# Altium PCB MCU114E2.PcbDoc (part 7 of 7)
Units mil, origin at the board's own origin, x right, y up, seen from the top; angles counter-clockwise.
Board outline 4153.94 x 2313.28 mil, 8 copper layers (Top Layer, GND 2, Signal Layer 3, Power 4, Power 5, Signal Layer 6, GND 7, Bottom), stack 61.2 mil thick; 444 components, 418 nets, 1811 pads, 981 vias.
Unrouted connection lines stored in the file: 3.
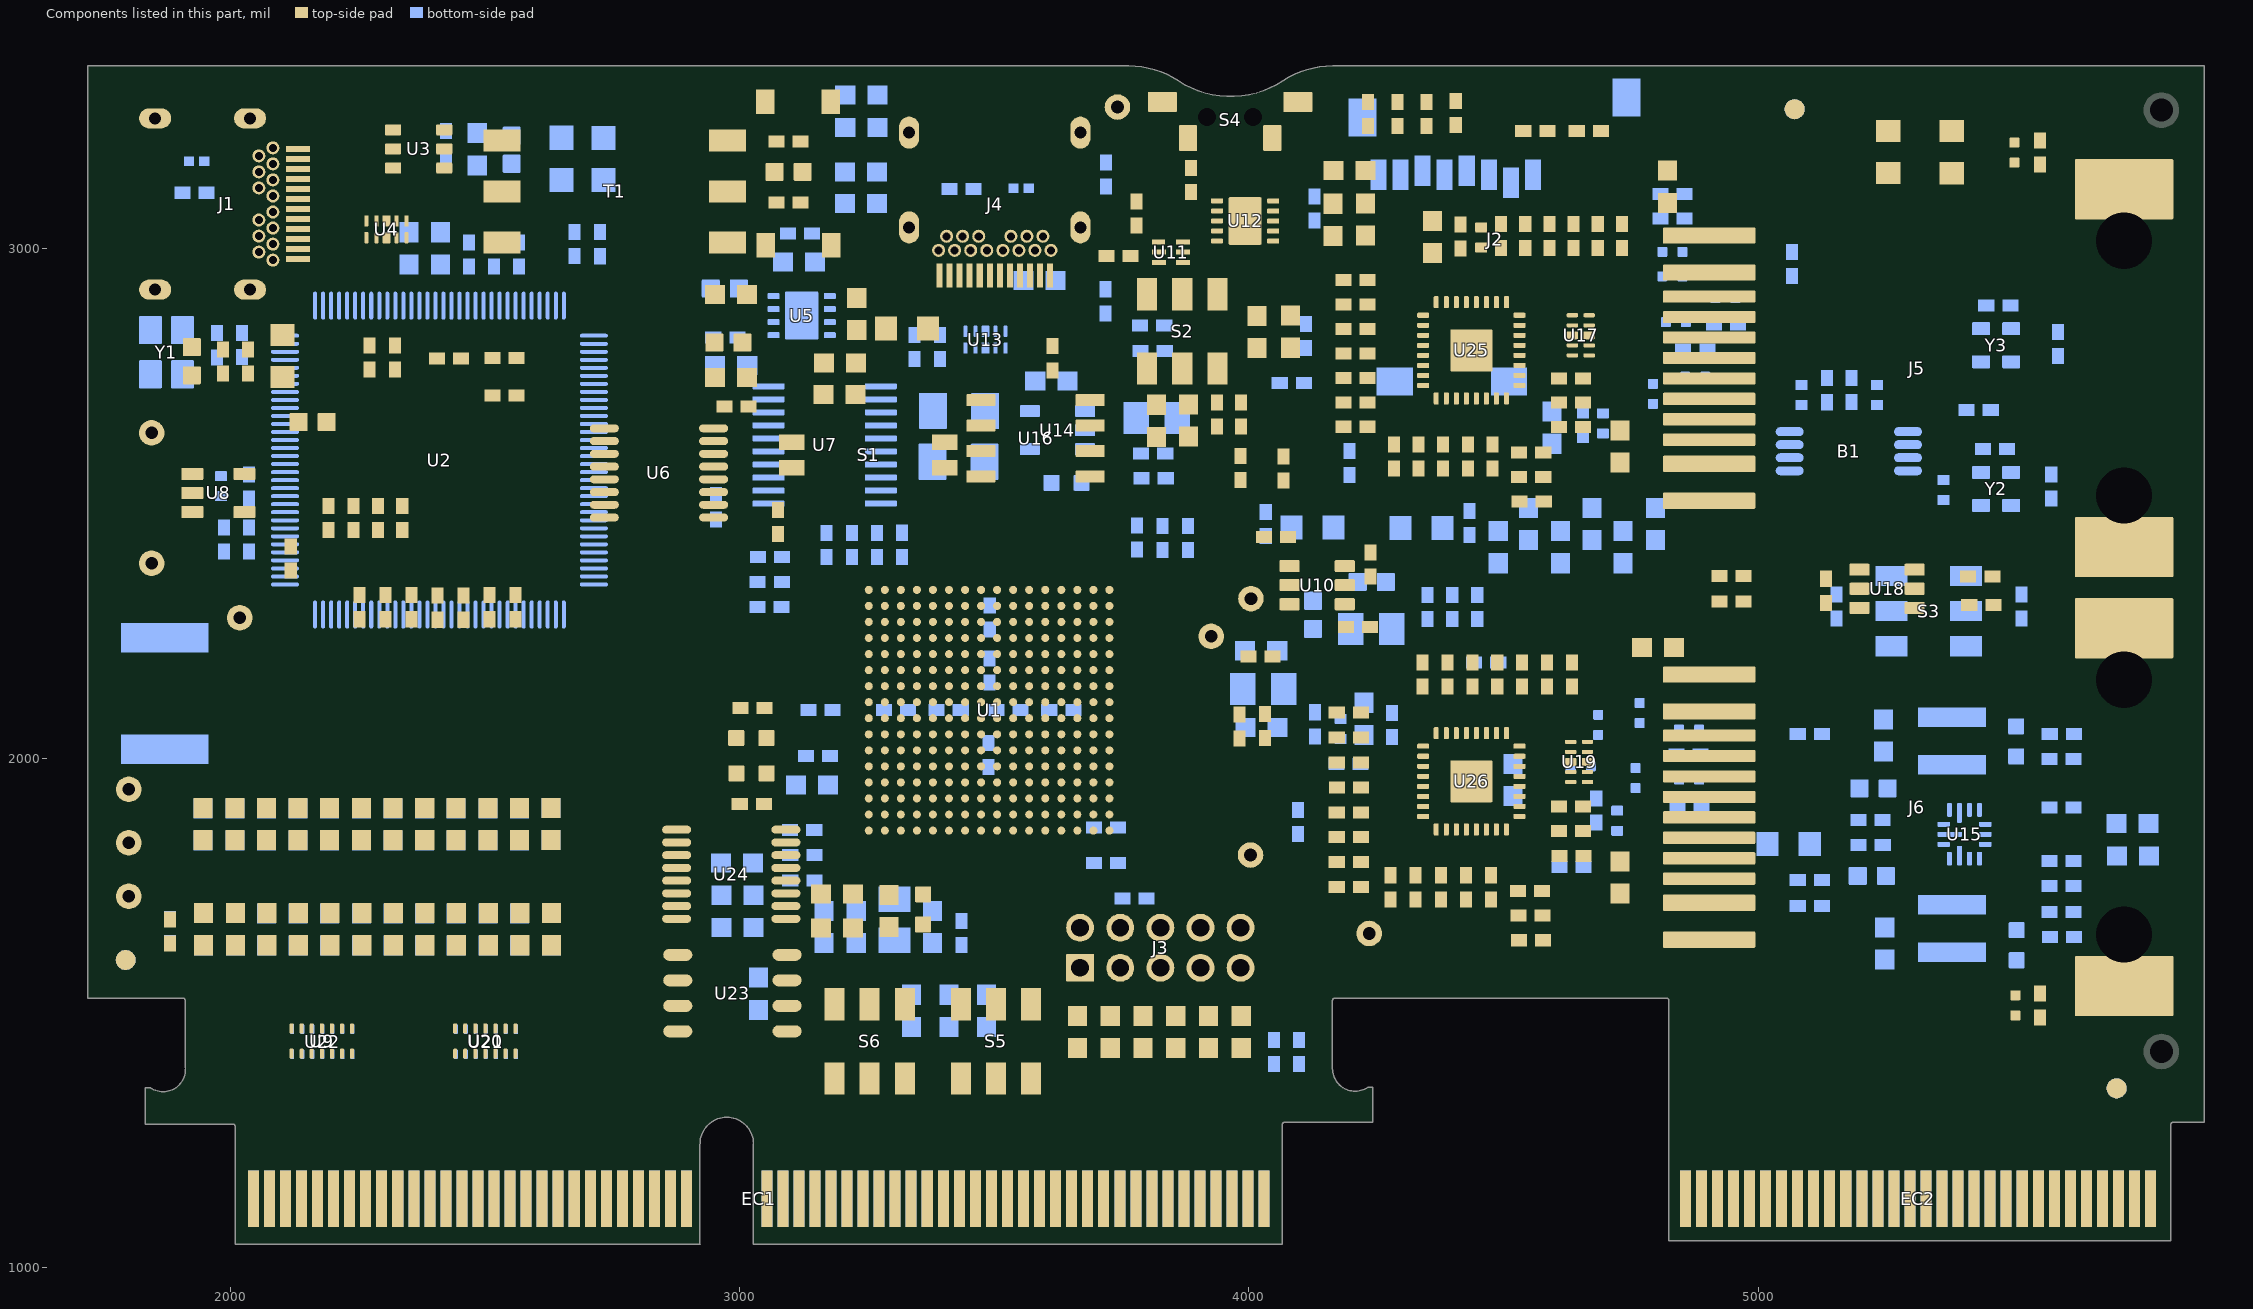
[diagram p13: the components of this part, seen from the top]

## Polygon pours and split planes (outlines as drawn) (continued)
5V0 on Bottom "BOTTOM_5V0_P229" (solid, remove dead copper, pour order 229): 5218.85,1959.23 5218.85,1896 5301,1896 5347,1896 5364.53,1878.47 5385.37,1878.47 5385.37,1940.04 5366.18,1959.23
5V0 on Bottom "BOTTOM_5V0_P230" (solid, remove dead copper, pour order 230): 5851.44,1971.69 5740.44,1971.69 5740.44,1851.69 5851.44,1851.69
EMU_5V0 on Bottom "BOTTOM_EMU_5V0_P231" (solid, remove dead copper, pour order 231): 2345.08,3216.85 2355.04,3216.85 2402.43,3216.85 2402.43,3207.9 2456.01,3207.9 2456.01,3189.27 2617.83,3189.27 2617.83,3074.27 2410.83,3074.27 2345.08,3140.02
5V0 on Bottom "BOTTOM_5V0_P232" (solid, remove dead copper, pour order 232): 3232.19,3339.27 3232.19,3232 3382,3232 3462.73,3151.27 3821.06,3151.27 3821.06,3339.27
EMU_GND on GND 2 "GND_2_EMU_GND_P206" (solid, remove dead copper, pour order 206): 1745.23,3346.77 2776.83,3346.77 2776.83,2365.27 2614.83,2203.27 1743.04,2203.27
ETH1_EARTH on GND 2 "GND_2_ETH1_EARTH_P172" (solid, remove dead copper, pour order 172): 5466,3228 5468,3230 5623,3230 5623,3332.84 5622.83,3333.01 5625.05,3335.23 5851.76,3335.23 5851.76,1337.49 5849.54,1335.27 5551.33,1335.27 5551.33,1598.1 5631.83,1598.1 5631.83,1728.84 5631.45,1729.22 5631.38,1729.16 4983.08,1729.16 4983.08,1806.03 5628.83,1806.03 5628.83,2186.78 5547.83,2267.78 5542.42,2267.78 5542.42,2430.79 5617.42,2505.79 5617.42,2593.86 5612.01,2599.27 4983.08,2599.27 4983.08,2696.27 5622.83,2696.27 5622.83,3075.27 5621.71,3074.15 5466.26,3074.15 5466.26,3229.26 5467,3230
GND on GND 2 "GND_2_GND_P227" (solid, remove dead copper, pour order 227): 1740.14,2050.63 1740.96,2051.46 2674.72,2051.46 2912.81,2305.52 2924.42,3360.1 5627.81,3355.97 5627.81,3074.15 5627.81,2694.47 4994.75,2694.47 4994.75,2597.93 5642.5,2597.93 5642.5,2517.86 5559.5,2434.86 5559.5,2266.44 5640.96,2184.98 5640.96,1817.39 5627.81,1804.23 4994.75,1804.23 4994.75,1727.82 5643.49,1727.82 5643.49,1593.18 5563.59,1593.18 5563.59,1545.84 5654.96,1454.47 5859.96,1454.47 5871.96,1442.47 5871.96,1304.47 5853.63,1286.13 5803.96,1286.13 5803.96,1061.47 4845.96,1061.47 4845.96,1504.75 4810.67,1540.04 4190.53,1540.04 4166.96,1516.47 4166.96,1366.47 4196.96,1336.47 4240.93,1336.47 4240.93,1286.13 4061.39,1286.13 4061.39,1055.47 3043.96,1055.47 3043.96,1260.36 3005.86,1298.47 2961.96,1298.47 2921.96,1258.47 2921.96,1062 2029.96,1061.47 2029.96,1280.49 1853.93,1280.49 1853.93,1309.44 1853.93,1340.47 1903.2,1340.47 1923.48,1360.75 1923.48,1540.04 1740.96,1538.47
EMU_GND on GND 7 "GND_7_EMU_GND_P189" (solid, remove dead copper, pour order 189): 1723.76,3352.27 2773.69,3352.27 2773.69,2361.12 2615.83,2203.27 1718.78,2203.27
GND on GND 7 "GND_7_GND_P223" (solid, remove dead copper, pour order 223): 1711.87,2049.75 2668.68,2049.75 2911.87,2292.93 2911.87,3339.75 5862.87,3339.75 5862.87,1399.27 5862.87,1283.27 5819.33,1283.27 5800.43,1264.37 5800.43,1034.29 4825.85,1034.29 4805.15,1054.99 4805.15,1508.27 4157.83,1508.27 4161.87,1504.23 4161.87,1363.27 4186.87,1343.27 4225.84,1343.27 4225.84,1274.29 4225.84,1264.37 4225.74,1264.27 4048.91,1264.27 4048.91,1030.29 4047.93,1031.27 3017.87,1031.27 3017.87,1243.12 2984.24,1276.75 2940.35,1276.75 2911.87,1248.27 2911.87,1042.27 2007.87,1042.27 2002.87,1037.27 2002.87,1269.27 1830.87,1269.27 1817.83,1282.31 1817.83,1342.27 1879.87,1342.27 1914.03,1376.43 1914.03,1535.75 1711.87,1535.75
VDDA_3V3 on Power 5 "POWER_5_VDDA_3V3_P176" (solid, remove dead copper, pour order 176): 1895.5,1554.5 1882,1568 1882,1949.33 1908.81,1976.14 2636.52,1976.14 2682.24,1930.41 2956.58,1930.41 2956.58,2068.27 3045.96,2157.65 3239.1,2157.65 3345.83,2050.92 3403.26,2050.92 3411.33,2042.86 3411.33,1987.27 3449.83,1948.77 3449.83,1911.66 3519.83,1841.66 3519.83,1671.79 3469.12,1621.08 3050.23,1621.08 3008.33,1579.17 3008.33,1292.33 2940.33,1292.33 2915.5,1267.5 2915.5,1063.5 2012.64,1063.5 2002.35,1073.79 2003.45,1074.89 2003.45,1280.06 1844.06,1280.06 1831.79,1292.33 1839.45,1299.99 1839.45,1350.61 1913.34,1350.61 1914.03,1351.3 1913.34,1550
VBUS_5V0 on Power 5 "POWER_5_VBUS_5V0_P207" (solid, remove dead copper, pour order 207): 3360.28,3165.77 3742.83,3165.77 3742.83,2775.28 3742.77,2775.34 3595.83,2775.34 3595.83,2695.9 3594.77,2694.83 3594.94,2694.66 3683.46,2694.66 3683.46,2516.61 3682.8,2517.27 3366.15,2517.27
ISO_Pout_5V0 on Power 5 "POWER_5_ISO_POUT_5V0_P218" (solid, remove dead copper, pour order 218): 2925.35,2938.68 2990,2938.68 2990,2816.64 3177.72,2816.64 3177.72,3106.79 3226.83,3155.9 3226.83,3332.27 2925.09,3332.27 2924.35,3333.01
EMU_3V3 on Power 5 "POWER_5_EMU_3V3_P228" (solid, remove dead copper, pour order 228): 1737.26,3345.27 2781.99,3345.27 2781.99,2369.43 2613.83,2201.27 1732.3,2201.27
3V3 on Power 5 "POWER_5_3V3_P246" (solid, remove dead copper, pour order 246): 1724.35,2052.27 2679.08,2052.27 2916.26,2300.45 2920.95,3363.27 5875.35,3363.27 5875.35,1422.79 5875.35,1306.79 5831.81,1306.79 5812.91,1287.89 5812.91,1057.81 4838.33,1057.81 4817.63,1078.51 4817.63,1531.79 4170.32,1531.79 4174.35,1527.75 4174.35,1386.79 4199.35,1366.79 4238.32,1366.79 4238.32,1297.81 4238.32,1287.89 4238.22,1287.79 4061.39,1287.79 4061.39,1053.81 4060.42,1054.79 3030.35,1054.79 3030.35,1266.64 2996.72,1300.27 2952.83,1300.27 2924.35,1271.79 2924.35,1060.79 2015.35,1060.79 2002.35,1073.79 2002.35,1292.79 1843.35,1292.79 1830.32,1305.83 1830.32,1365.79 1892.35,1365.79 1914.35,1387.79 1914.35,1541.79 1724.35,1541.79

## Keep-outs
Keep-Out Layer:
  text ".Layer_Name" at -765.05,-899.49 h60

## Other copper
Top Layer:
  pour cut-out: 5005.32,1364.09 5050.83,1364.09 5050.83,1341.83 5008.77,1341.83
  pour cut-out: 3376,1343 3386,1333 3386,1209 3345.1,1209 3333.33,1220.77
  pour cut-out: 3336,1414 3375.72,1414 3376,1414.28 3376,1343 3342,1343 3339,1346
  pour cut-out: 2013.22,2811 2013.22,2760.31 1935.08,2760.31 1935.08,2810.6
  pour cut-out: 3998.12,1341.27 4025,1314.39 4025,1285 4108,1368 4064,1412 4064,1407.15
  pour cut-out: 2035.26,1075.15 2897.18,1075.15 2897.18,1071.04 2035.26,1071.04
  pour cut-out: 3052.19,1075.15 4036.15,1075.15 4032.62,1071.62 4032.62,1071.04 3052.19,1071.04
  pour cut-out: 3816.28,1803 3823.96,1803 3824.37,1803.42 3916.79,1711 3912.19,1711 3902.4,1701.21 3815.51,1788.09 3815.51,1801.15
  pour cut-out: 3264.59,1929.58 3264.59,1924.78 3286.84,1902.53 3272.61,1888.29 3239.44,1888.29 3231.94,1895.78 3264.51,1928.35
  pour cut-out: 3390.41,1878.36 3422.28,1878.36 3426.45,1874.19 3420.14,1867.88 3420.14,1812.39 3399.98,1812.39 3390.41,1821.95
  pour cut-out: 3360.96,1947.64 3367.56,1947.64 3411.33,1947.64 3411.33,1873.75 3411.33,1878.36 3401.09,1878.36 3361.06,1878.36 3361.05,1887.28 3360.96,1942
  pour cut-out: 3476.63,2059.92 3482.38,2065.66 3503.01,2065.66 3503.01,1798.5 3496.8,1792.3 3494.41,1794.68 3479,1794.68 3479,1860.24 3462.72,1876.52 3460.39,1874.19 3434.05,1874.19 3434.05,1929.62 3467.44,1963.01 3467.44,2054.98 3472.38,2059.92
  pour cut-out: 3520.86,2107.12 3738.77,2107.12 3738.77,2086.67 3739.25,2086.19 3738.59,2085.52 3513.76,2085.52 3513.76,2100.03
  pour cut-out: 3471.51,2317.63 3508.13,2317.63 3508.13,2194.55 3502.35,2188.77 3502.11,2189.02 3442.82,2189.02 3442.82,2294.84 3467.34,2319.36
  pour cut-out: 2900.52,2654.48 2904,2651 2921.97,2651 2921.97,2463.94 2921.17,2463.14 2915.83,2468.48 2898.52,2468.48 2898.52,2652.48
  pour cut-out: 3894,2334 3900.17,2327.83 3945.77,2327.83 3945.77,2305.21 3931.83,2291.27 3928.06,2295.04 3854.17,2295.04 3854.17,2303.35 3885.86,2335.04
  text ".Layer_Name" at -733,-894 h60
Signal Layer 3:
  text ".Layer_Name" at -777.17,-912.73 h60
GND 2:
  text ".Layer_Name" at -742.17,-892.73 h60
GND 7:
  text ".Layer_Name" at -737.17,-889.73 h60
Signal Layer 6:
  text ".Layer_Name" at -725.17,-888.73 h60
Power 4:
  text ".Layer_Name" at -713.17,-903.73 h60
Power 5:
  text ".Layer_Name" at -737.17,-889.73 h60
Bottom:
  pour cut-out: 2467.49,1825.44 2467.88,1825.83 2481.98,1825.83 2481.98,1790.48 2471.53,1780.03
  pour cut-out: 3189.86,1675.79 3256.79,1675.79 3257,1676 3257,1693 3191,1693 3190,1692
  pour cut-out: 4070.11,1309.75 4037.25,1309.75 4037,1310 4037,1297.07 4043.11,1290.96
  pour cut-out: 3889.1,2345.28 3889.1,2328.18 3890.01,2327.27 3887.58,2324.83 3874.17,2324.83 3871,2328
  pour cut-out: 5591.94,1920.5 5592,1920.56 5592,1925 5585,1925 5585,1920
  pour cut-out: 3159.62,2872.97 3166.65,2880 3219,2880 3219,2859.31 3181.87,2822.18 3159.35,2822.18
  pour cut-out: 3405.48,1555 3446,1555 3446,1404.92 3440.08,1399 3402,1399
  pour cut-out: 3027.22,2693.53 3027.86,2694.16 3092.58,2694.16 3113,2673.75 3113,2658 3125,2646 3125,2526.37 3104.13,2505.5 3099.71,2509.93 3027.22,2509.93 3027.22,2664.43
  pour cut-out: 3230.98,2551.02 3309.91,2551.02 3313.87,2547.07 3313.87,2495.89 3263.3,2495.89 3236.95,2522.23 3230.98,2522.23
  pour cut-out: 3151.38,2646.02 3231.45,2726.08 3310.74,2726.08 3313.87,2722.95 3313.87,2649.43 3212.85,2649.43 3190.42,2627 3153.22,2627
  pour cut-out: 3739.96,2601.22 3761.5,2622.77 3888.96,2622.77 3888.96,2530 3739.96,2530
  pour cut-out: 5368.98,1336.77 5372.08,1339.87 5388.48,1339.87 5388.48,1290.83 5390.44,1288.87 5381.76,1280.19 5371.77,1280.19 5371.77,1333.98
  pour cut-out: 5793,1238 5793,1196 5792.39,1195.39 5781.08,1195.39 5781.08,1228.92 5772,1238
  text ".Layer_Name" at -732.17,-905.73 h60

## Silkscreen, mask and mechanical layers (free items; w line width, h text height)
Top Overlay:
  region: 5460,1316 5315,1316 5315,1251 5460,1251
  text "-----------------------------" at 2769.47,3377.07 h35 r269.64
  text "------------------------------" at 2900.47,3357.07 h35 r269.64
  text "ETH1_EARTH" at 5520,3295.1 h40
  text "5V0" at 3706,3205.61 h55
  text "P0" at 4979,3161.66 h55
  text "XRSn" at 3934,3146.61 h55
  text "0" at 3743,2934.49 h40
  text "1" at 3983.6,2934.27 h40
  text "POS 1" at 3651.49,2865.05 h40
  text "POS 2" at 3651.49,2789.12 h40
  text "0" at 3743,2733.64 h40
  text "1" at 3983.6,2733.42 h40
  text "1" at 3067.53,2645 h40
  text "0" at 3424,2645.44 h40
  text "JTAG" at 2993.94,2609.39 h35
  text "UART" at 2991.54,2559.97 h35
  text "EMU_5V0" at 1797.67,2525.61 h55 r90
  text "0" at 3424,2523.57 h40
  text "1" at 3066.53,2523.13 h40
  text "VDD_1V2" at 3824.05,2354.77 h55
  text "EMU_3V3" at 1747.87,2307.2 h55
  text "XRSn" at 3766,2221.61 h55
  text "Cold Side" at 2620.69,2214.52 h55 r47.05
  text "EMU_GND" at 1896.18,2212.97 h55
  text "-------" at 2626.55,2182.98 h35 r45.17
  text "-------------------------" at 1735,2176.51 h35
  text "Hot Side" at 2772.82,2089.6 h55 r45.91
  text "----------" at 2688.55,2044.71 h35 r46.53
  text "---------------------------" at 1722.67,2037.45 h35
  text "3V3" at 1765,1974.61 h55
  text "GND" at 1746.93,1865.81 h55
  text "VDDIO_3V3" at 3767.15,1853.34 h55
  text "HSEC_5V0" at 1832,1741 h55
  text "Int Vref_B" at 3404.18,1579.4 h55
  text "Ext Vref" at 3166.05,1574.8 h55
  text "ERRORSTS" at 4097,1548.61 h55
  text "1" at 3144.77,1536.88 h40
  text "0" at 3365.62,1537.1 h40
  text "1" at 3391.01,1536.88 h40
  text "0" at 3605.26,1534.86 h40
  text "P1" at 4985.61,1482 h55
  text "ETH1_EARTH" at 5515,1415.1 h40
  text "C2000 F28P65x controlCARD" at 4886.44,1348.73 h60
  text "1" at 3140.69,1333.79 h40
  text "0" at 3361.31,1334.02 h40
  text "1" at 3386.69,1333.79 h40
  text "0" at 3600.95,1331.77 h40
  text "57" at 3029.65,1281.71 h50
  text "55" at 2873,1281.05 h50
  text "179" at 5739,1280.77 h50
  text "1" at 2037.96,1280.49 h50
  text "119" at 3992.17,1280.18 h50
  text "121" at 4831,1280.49 h50
  text "Int Vref_A" at 3145.31,1277.96 h55
  text "Int Vref_C" at 3415.83,1277.96 h55
  text "REV E2 -" at 5078.48,1269.48 h60
  text ".Layer_Name" at -752.17,-886.73 h60
Bottom Overlay:
  text "-------------------------------" at 2899.47,3382.07 h35 r269.64
  text "-----------------------------" at 2769.47,3376.07 h35 r269.64
  text "1" at 5216.43,2389.18 h40
  text "1" at 5461.03,2389.18 h40
  text "GPIO 84" at 5188.44,2221 h40 r270
  text "GPIO 72" at 5453.44,2221.07 h40 r270
  text "-------" at 2626.55,2182.98 h35 r45.17
  text "-------------------------" at 1737,2176.51 h35
  text "0" at 5203.35,2176.87 h40
  text "0" at 5447.95,2176.87 h40
  text "BOOT" at 5382,2140.44 h40
  text "----------" at 2688.54,2044.71 h35 r46.5
  text "---------------------------" at 1726.5,2035.51 h35
  text "TMDSCNCD28P65X" at 4936,1671 h70
  text "'.PRJ_Number'.PCB_Rev" at 4804.2,1603.33 h70
  text "58" at 3071.19,1281.57 h50
  text "56" at 2917.99,1280.94 h50
  text "122" at 4897,1281 h50
  text "2" at 2054.62,1280.29 h50
  text "120" at 4059.36,1279.98 h50
  text "180" at 5807.08,1280.15 h50
  text ".Layer_Name" at -750.17,-896.73 h60
Top Paste:
  text ".Layer_Name" at -765.05,-899.49 h60
Bottom Paste:
  text ".Layer_Name" at -765.05,-899.49 h60
Top Solder:
  rectangle: 2000,1032 2933,1191.2
  rectangle: 4814,1032 5819,1191.2
  rectangle: 3017,1032 4075,1191.2
  text ".Layer_Name" at -765.05,-899.49 h60
  text ".Layer_Name" at -765.05,-899.49 h60
Bottom Solder:
  rectangle: 4814,1032 5819,1191.2
  rectangle: 2000,1032 2932,1191.2
  rectangle: 3018,1031.6 4075,1190.8
  text ".Layer_Name" at -765.05,-899.49 h60
Drill Guide:
  text ".Layer_Name" at -765.05,-899.49 h60
M1 Board Outline:
  lines w10: 1906.8,1391.27 1906.8,1524.27 1715.83,1524.27 1715.83,3364 3767,3364 ; 1907.3,1391.29 cw(c1868.35,1389.36) 1844.8,1358.27 1828.8,1358.27 1828.8,1277 2005,1277 2005,1045.98 ; 2010.84,1041.04 2922.46,1041.04 ; 2927.26,1047.48 2927.26,1241.96 ; 2927.36,1242.93 cw(c2974.85,1242.55) 3022.33,1242.93 3022.33,1045.77 ; 3027.41,1040.69 4070.11,1040.76 ; 3764,3364 cw(c3764,3182.33) 3864,3334 ccw(c3964,3485.67) 4064,3334 cw(c4164,3182.33) 4164,3364 ; 4070.11,1046.6 4070.11,1276.93 ; 4070.11,1280.27 4247.8,1280.27 4247.8,1359.27 4231.8,1359.27 cw(c4208.3,1390.39) 4169.3,1390.27 ; 4167,3364 5879.8,3364 5879.8,1280.37 5814.39,1280.37 5814.39,1048.27 4819.11,1048.27 4819.11,1524.27 4168.8,1524.27 4168.8,1487.86 4168.8,1390.27
  text ".Layer_Name" at -765.05,-899.49 h60
M2 Board Dimensions:
  rectangle: -1342.05,-315.99 -1217.05,-190.99
  rectangle: -1217.05,-440.99 -842.05,-315.99
  lines w5: 1998.81,1311.29 2008.81,1301.29 ; 2018.81,1311.29 2008.81,1301.29 ; 2178.81,1346.29 2033.81,1346.29 2008.81,1321.29 2008.81,1301.29 ; 4088.81,1251.29 4088.81,1266.29 ; 4103.81,1266.29 4088.81,1266.29 ; 4103.81,1561.29 4103.81,1526.29 4123.81,1526.29 4153.81,1526.29 ; 4143.81,1516.29 4153.81,1526.29 ; 4143.81,1536.29 4153.81,1526.29 ; 4338.81,1576.29 4348.81,1566.29 4823.81,1566.29 4823.81,1546.29 4823.81,1531.29 ; 4473.81,691.29 4473.81,861.29 4118.81,1216.29 4118.81,1236.29 4088.81,1266.29 ; 4813.81,1541.29 4823.81,1531.29 ; 4833.81,1541.29 4823.81,1531.29 ; 5778.81,1396.29 5778.81,1371.29 5798.81,1351.29 5818.81,1331.29 5818.81,1316.29 5818.81,1291.29 ; 5808.81,1301.29 5818.81,1291.29 ; 5828.81,1301.29 5818.81,1291.29
  lines w7: -1342.05,-315.99 -342.05,-315.99 ; -1217.05,-440.99 -1217.05,-190.99 ; -1092.05,-440.99 -1092.05,-190.99 ; -842.05,-440.99 -842.05,-190.99 ; -592.05,-440.99 -592.05,-190.99 ; -1342.05,-440.99 -342.05,-440.99 -342.05,-190.99 -1342.05,-190.99 -1342.05,-440.99
  lines w10: 1923.81,1566.29 1923.81,1546.29 ; 1943.81,1546.29 1923.81,1546.29 ; 2018.81,1561.29 1938.81,1561.29 1923.81,1546.29 ; 8495.95,186.01 8563.95,186.01 ; 8537.95,157.01 8564.95,185.01 ; 8537.95,216.01 8564.95,186.01 ; 8571.95,1531.01 8639.95,1613.01 ; 8573.95,139.01 8573.95,461.01 ; 8573.95,502.01 8623.95,448.01 8733.95,448.01 8780.95,505.01 ; 8573.95,504.01 8573.95,1534.01 ; 8638.95,1614.01 8702.95,1527.01 ; 8656.95,354.01 8724.95,354.01 ; 8698.95,325.01 8725.95,353.01 ; 8698.95,384.01 8725.95,354.01 ; 8703.95,1526.01 8775.95,1616.01 ; 8734.95,139.01 8734.95,421.01 ; 8780.95,504.01 8780.95,1534.01 8780.95,1619.01 ; 8781.95,139.01 8781.95,461.01 ; 8787.92,1154.63 cw(c8731.95,447.01) 9171.29,1004.54 ; 8789.8,1153.26 ccw(c8929.55,1387.92) 8840.67,1129.67 ; 8789.95,189.01 8816.95,159.01 ; 8789.95,190.01 8816.95,218.01 ; 8789.95,1160.01 cw(c8822.4,986.03) 8852.67,1160.4 ; 8791.95,190.01 8859.95,190.01 ; 8791.95,353.01 8818.95,323.01 ; 8791.95,354.01 8818.95,382.01 ; 8793.95,354.01 8861.95,354.01 ; 8807.95,543.01 9270.95,1115.01 ; 9117.95,1019.01 ccw(c9255.48,1359.44) 9172.61,1001.75 ; 9135.2,1052.31 cw(c9018.34,918.86) 9173.95,1004
  text "X2" at 4228.81,1681.29 h60
  text "R 39.00" at 4004.83,1593.27 h60
  text "R 39.00" at 2048.81,1541.29 h60
  text "R 39.00" at 5458.81,1416.29 h60
  text "R 39.00" at 2208.81,1311.29 h60
  text "30" at 8976.95,1175.01 h60
  text "R 39.00" at 4343.81,606.29 h60
  text "18MIL" at 8902.95,326.01 h60
  text "62MIL" at 8895.95,162.01 h60
  text "GOLD FINGER" at 8414.95,-74.99 h60
  text "SIDE VIEW" at 8468.95,-187.99 h60
  text ".Layer_Name" at -765.05,-899.49 h60
M3 3D STEP Top:
  text ".Layer_Name" at -765.05,-899.49 h60
M4 3D STEP Bottom:
  text ".Layer_Name" at -765.05,-899.49 h60
M5 Assembly Top:
  lines w10: -1634.05,-971.16 4965.95,-971.16 ; -1634.05,-767.83 4967.95,-767.83 ; -1634.05,-564.49 -1634.05,-1174.49 2370.95,-1174.49 4967.95,-1174.49 4967.95,-564.5 -1633.55,-564.5 -1633.55,-1174.49 -58.05,-1174.49 ; 830.95,-1174.49 830.95,-564.5 ; 2097.95,-767.83 2097.95,-564.5 ; 2937.95,-767.83 2937.95,-564.5 ; 3559.95,-1180.99 3559.95,-978.16
  text "COMPONENTS MARKED 'DNP' SHOULD NOT BE POPULATED." at -188.55,-359.49 h60
  text "ASSEMBLY VARIANT:" at -189.05,-474.99 h60
  text ".VariantName" at 846.95,-474.99 h60
  text "PCB VIEWED FROM TOP SIDE" at -1570.55,-696.66 h60
  text "BOARD #:" at 905.95,-696.66 h60
  text ".PRJ_Number" at 1451.45,-696.66 h60
  text "REV:" at 2295.95,-696.66 h60
  text ".PCB_Rev" at 2587.45,-696.66 h60
  text "SVN REV:" at 3133.95,-696.66 h60
  text "TID #:" at 905.95,-899.99 h60
  text ".TID" at 1451.45,-899.99 h60
  text "PLOT NAME =" at -1570.55,-1105.33 h60
  text ".plot_File_Name" at -765.05,-1105.33 h60
  text "GENERATED    :" at 907.95,-1105.33 h60
  text ".Print_Date" at 1777.45,-1105.33 h60
  text ".Print_Time" at 2506.45,-1105.33 h60
  text "TEXAS INSTRUMENTS" at 3770.95,-1105.33 h60
M6 Assembly Bottom:
  lines w10: -1634.55,-768.33 4967.45,-768.33 ; -1632.55,-971.66 4967.45,-971.66 ; -226.55,-1181.49 -226.55,-978.66 ; 395.45,-768.33 395.45,-565 ; 1235.45,-768.33 1235.45,-565 ; 2502.45,-1174.99 2502.45,-565 ; 3391.45,-1174.99 4966.95,-1174.99 4966.95,-564.99 -1634.55,-565 -1634.55,-1174.99 962.45,-1174.99 4967.45,-1174.99 4967.45,-564.99
  text "COMPONENTS MARKED 'DNP' SHOULD NOT BE POPULATED." at 4759.95,-358.99 h60
  text ".VariantName" at 3715.95,-474.99 h60
  text "ASSEMBLY VARIANT:" at 4754.95,-474.99 h60
  text "SVN REV:" at 199.45,-697.16 h60
  text ".PCB_Rev" at 745.95,-697.16 h60
  text "REV:" at 1037.45,-697.16 h60
  text ".PRJ_Number" at 1881.95,-697.16 h60
  text "BOARD #:" at 2427.45,-697.16 h60
  text ".TID" at 1881.95,-900.49 h60
  text "TID #:" at 2427.45,-900.49 h60
  text "TEXAS INSTRUMENTS" at -437.55,-1105.83 h60
  text ".Print_Time" at 826.95,-1105.83 h60
  text ".Print_Date" at 1555.95,-1105.83 h60
  text "GENERATED    :" at 2425.45,-1105.83 h60
  text ".plot_File_Name" at 4098.45,-1105.83 h60
  text "PLOT NAME =" at 4903.95,-1105.83 h60
M9 Title Sheet:
  drawing of 57 lines, arcs and shapes, not listed
  text "1" at -602.21,7995.51 h70
  text "2" at 1893.45,7995.51 h70
  text "3" at 4382.79,7995.51 h70
  text "4" at 6889.46,7995.51 h70
  text "5" at 9388.45,7995.51 h70
  text "6" at 11893.45,7995.51 h70
  text "A" at -1758.55,6852.51 h70
  text "A" at 13041.45,6852.51 h70
  text "B" at -1758.55,4472.51 h70
  text "B" at 13041.45,4472.51 h70
  text "C" at -1758.55,2097.51 h70
  text "C" at 13041.45,2097.51 h70
  text "PROJECT TITLE:" at 10001.45,236.51 h45
  text ".PRJ_Title" at 10051.45,103.18 h70
  text "DESIGNED FOR:" at 10001.45,-64.49 h45
  text ".PRJ_Customer" at 10051.45,-204.49 h70
  text "D" at -1758.55,-272.49 h70
  text "D" at 13041.45,-272.49 h70
  text "FILE NAME:" at 10001.45,-364.49 h45
  text ".PCB_File_Name_No_Path" at 10051.45,-484.49 h70
  text "Texas Instruments (TI) and/or its licensors do not warrant the accuracy or completeness of this specification" at 5031.95,-646.33 h45
  text "ENGINEER:" at 10001.45,-654.49 h45
  text "LAYOUT BY:" at 11506.45,-654.49 h45
  text "or any information contained therein. TI and/or its licensors do not warrant that this design will meet" at 4986.97,-759 h45
  text ".PRJ_Engineer" at 10051.45,-809.49 h70
  text ".PCB_Layout" at 11556.95,-809.49 h70
  text "the specifications, will be suitable for your application or fit for any particular purpose, or will operate in" at 4986.97,-871.66 h45
  text ".Layer_Name" at -765.05,-899.49 h60
  text "ALTIUM DESIGNER VERSION:" at 11506.45,-964.49 h45
  text "an implementation. TI and/or its licensors do not warrant that the design is production worthy. You should" at 4986.97,-984.33 h45
  text "completely validate and test your design implementation to confirm the system functionality for your application." at 5031.95,-1096.99 h45
  text ".print_Scale" at 10051.45,-1097.82 h70
  text ".Application_BuildNumber" at 11556.95,-1097.82 h70
  text "1" at -602.21,-1304.49 h70
  text "2" at 1893.45,-1304.49 h70
  text "3" at 4382.79,-1304.49 h70
  text "4" at 6889.46,-1304.49 h70
  text "5" at 9388.45,-1304.49 h70
  text "6" at 11893.45,-1304.49 h70
M10 Fab Notes:
  drawing of 185 lines, arcs and shapes, not listed
  text "DESIGN INFORMATION" at 11039.97,6455.18 h60
  text "5" at 11493.81,6326.29 h60
  text "MIN. TRACK WIDTH:" at 10395.41,6323.05 h60
  text "MIL" at 11646.41,6323.05 h60
  text "4" at 11503.81,6206.29 h60
  text "MIN. CLEARANCE:" at 10395.41,6198.93 h60
  text "MIL" at 11646.41,6198.93 h60
  text "MIN. VIA PAD SIZE:" at 10395.41,6074.8 h60
  text "18" at 11461.66,6074.8 h60
  text "MIL" at 11646.41,6074.8 h60
  text "0.05mm (2MIL)" at 11090.41,5944.9 h60
  text "MINIMUM ANNULAR RING" at 10066.18,5936.68 h60
  text "EXTERNAL" at 11798.41,5936.68 h60
  text "PER" at 10266.18,5826.55 h60
  text "IPC-D-275 CLASS 2 LEVEL C" at 10486.18,5826.55 h60
  text "MIL, HOLES" at 11974.41,5726.07 h60
  text "+/-" at 11581.95,5717.49 h60
  text "+/-" at 12435.95,5717.49 h60
  text "REGISTRATION TOLERANCES:" at 10066.18,5716.42 h60
  text "METAL" at 11265.95,5716.42 h60
  text "5" at 11842.15,5716.43 h60
  text "3" at 12675.15,5716.43 h60
  text "MIL" at 12791.41,5716.42 h60
  text "HOLE SIZE TOLERANCE (UNLESS OTHERWISE SPECIFIED):" at 10066.18,5618.11 h60
  text "+/-" at 12435.95,5615.24 h60
  text "3" at 12675.15,5614.17 h60
  text "MIL" at 12791.41,5614.17 h60
  text "MATERIAL:" at 9991.41,5476.52 h60
  text "FR-4 High Tg" at 10977.85,5348 h60
  text "X" at 10833.41,5340.01 h60
  text "FR-408" at 10412.41,5335.49 h60
  text "OTHER" at 11900.41,5335.49 h60
  text "62 MIL (1.57mm) +/-10%" at 10732.51,5192.46 h60
  text "X" at 10612.41,5190.01 h60
  text "THICKNESS:" at 10066.18,5184.24 h60
  text "OTHER" at 12017.41,5184.24 h60
  text "TOLERANCE:" at 10066.18,5045.93 h60
  text "X" at 10914.41,5045.93 h60
  text "ANSI IPC-6012 TYPE 3 CLASS 2" at 11092.43,5045.93 h60
  text "OTHER +/-" at 11092.41,4901.74 h60
  text "BOW & TWIST:" at 10066.18,4756.55 h60
  text "X" at 10914.41,4756.55 h60
  text "ANSI IPC-6012 TYPE 3 CLASS 2" at 11092.43,4756.55 h60
  text "OTHER +/-" at 11092.41,4609.85 h60
  text "DRILLING:" at 9991.41,4479.23 h60
  text "NC_DRILL FILES" at 11752.41,4374.05 h60
  text "REFERENCE:" at 10066.18,4370.11 h60
  text "X" at 10723.41,4370.01 h60
  text "AS SHOWN" at 10901.41,4370.11 h60
  text "X" at 11624.41,4370.11 h60
  text "OTHER" at 12050.41,4227.86 h60
  text "PTH COPPER THICKNESS:" at 10065.86,4224.33 h60
  text "X" at 11205.09,4224.33 h60
  text "20-30 um" at 11333.09,4224.33 h60
  text "BOARD FINISH:" at 9991.41,4076.73 h60
  text "SILKSCREEN:" at 10146.63,3966.6 h60
  text "X" at 11104.41,3966.6 h60
  text "TOP" at 11221.41,3966.6 h60
  text "X" at 11614.41,3966.6 h60
  text "BOTTOM" at 11732.41,3966.6 h60
  text "SILKSCREEN COLOR:" at 10146.63,3811.42 h60
  text "X" at 11103.41,3811.42 h60
  text "WHITE" at 11221.41,3811.42 h60
  text "OTHER" at 11732.41,3811.42 h60
  text "BLUE" at 12387.41,3677.97 h60
  text "GREEN" at 11352.41,3667.97 h60
  text "X" at 11824.41,3667.97 h60
  text "OTHER" at 11970.41,3667.97 h60
  text "SOLDER RESIST COLOR:" at 10146.63,3661.1 h60
  text "X" at 11824.81,3515.99 h60
  text "MATTE" at 11352.41,3513.72 h60
  text "SEMI-GLOSS" at 11969.95,3513.08 h60
  text "IMMERSION GOLD (ENIG)" at 11052.41,3340.94 h60
  text "ENEPIG" at 12389.95,3333.72 h60
  text "SURFACE FINISH:" at 9991.41,3332.72 h60
  text "X" at 10874.41,3332.72 h60
  text "IMM. TIN/SILVER OR EQUIV" at 10320.95,3195.41 h60
  text "HARD GOLD OVER NICKEL 30u/80u, ON EDGEFINGERS" at 10695.37,3042.4 h60
  text "X" at 10164.41,3032.72 h60
  text "OTHER" at 10342.41,3031.47 h60
  text "ARRAY/PANEL:" at 9991.41,2896.09 h60
  text "CUT AND TRIM PER M1 BOARD OUTLINE" at 11052.41,2887.87 h60
  text "N.C. ROUTE" at 11052.41,2751.9 h60
  text "X" at 11740.41,2751.9 h60
  text "V. SCORE" at 11918.41,2751.9 h60
  text "CERTIFICATION:" at 9991.41,2622.78 h60
  text "MATERIALS AND WORKMANSHIP FOR ALL PCBS" at 10716.41,2622.78 h60
  text "TO MEET OR EXCEED THE REQUIREMENTS OF:" at 10716.41,2528.71 h60
  text "X" at 10353.92,2400.09 h60
  text "ANSI IPC-A-600F CLASS ->" at 10481.91,2400.09 h60
  text "X" at 12129.92,2400.09 h60
  text "2" at 12239.91,2400.09 h60
  text "1" at 11924.91,2398.59 h60
  text "3" at 12593.91,2398.59 h60
  text "RJ1 and RJ2 : NPTH on SMT pads are intentional per manufacturers footprint.  SMT pad copper may be pulled back 5-8Mil from holes as needed for processing." at 6879,2297 h59
  text "X" at 11165.92,2252.4 h60
  text "RoHS" at 11293.91,2252.4 h60
  text "OTHER" at 11938.32,2252.4 h60
  text "PER ORDER" at 12335.37,2252.4 h60
  text "ALL BOARDS MUST MEET OR EXCEED UL94-V0 REQUIREMENTS." at 10018.95,2098.57 h60
  text "PCB MUST BEAR THE UL94V-0 UL REGISTERED MATERIAL ID NUMBER" at 10018.95,1982.51 h60
  text "ADDITIONAL REQUIREMENTS:" at 9991.41,1813.08 h60
  text "REQUIRED" at 11773.41,1691.63 h60
  text "BARE BOARD ELEC. TEST:" at 10006.18,1688.77 h60
  text "NONE" at 11311.91,1688.77 h60
  text "X" at 12247.95,1689.01 h60
  text "PER ORDER" at 12365.41,1688.77 h60
  text "X" at 10062,1441 h60
  text "ALL LAYERS 6.1 MIL WIDE, 6 MIL SPACE / TRACES REQUIRE 90 OHM DIFFERENTIAL IMPEDANCE" at 10267,1378 h60
  text "X" at 10064.92,1241.09 h60
  text "ALL LAYERS 4.9 MIL WIDE, 6 MIL SPACE / TRACES REQUIRE 50 OHM DIFFERENTIAL IMPEDANCE" at 10182,1191 h60
  text "X" at 10068.92,1045.09 h60
  text "OUTER LAYERS 6.2 MIL WIDE, 6 MIL SPACE / TRACES REQUIRE 100 OHM DIFFERENTIAL IMPEDANCE" at 10190,997 h60
  text "X" at 10070.92,880.09 h60
  text "ALL LAYERS 5.2 MIL WIDE, 6 MIL SPACE / TRACES REQUIRE 50 OHM SE  IMPEDANCE MATCHING" at 10261,825 h60
  text ".Layer_Name" at -765.05,-899.49 h60
M11 Gerber Information:
  lines w10: -1634.05,-971.16 4965.95,-971.16 ; -1634.05,-767.83 4967.95,-767.83 ; -1634.05,-564.49 -1634.05,-1174.49 2370.95,-1174.49 4967.95,-1174.49 4967.95,-564.5 -1633.55,-564.5 -1633.55,-1174.49 -58.05,-1174.49 ; 830.95,-1174.49 830.95,-564.5 ; 2097.95,-767.83 2097.95,-564.5 ; 2937.95,-767.83 2937.95,-564.5 ; 3559.95,-1180.99 3559.95,-978.16
  text "ALL ARTWORK VIEWED FROM TOP SIDE" at -1570.55,-696.66 h60
  text "BOARD #:" at 905.95,-696.66 h60
  text ".PRJ_Number" at 1451.45,-696.66 h60
  text "REV:" at 2295.95,-696.66 h60
  text ".PCB_Rev" at 2587.45,-696.66 h60
  text "SVN REV:" at 3133.95,-696.66 h60
  text "LAYER NAME =" at -1570.55,-899.49 h60
  text "TID #:" at 905.95,-899.99 h60
  text ".TID" at 1451.45,-899.99 h60
  text "PLOT NAME =" at -1570.55,-1105.33 h60
  text ".plot_File_Name" at -765.05,-1105.33 h60
  text "GENERATED    :" at 907.95,-1105.33 h60
  text ".Print_Date" at 1777.45,-1105.33 h60
  text ".Print_Time" at 2506.45,-1105.33 h60
  text "TEXAS INSTRUMENTS" at 3770.95,-1105.33 h60
M12 Stackup:
  drawing of 503 lines, arcs and shapes, not listed
  text "Layer" at 5321.35,6821 h60
  text "Name" at 5731.26,6821 h60
  text "Material" at 6671,6821 h60
  text "Thickness" at 7530.77,6821 h60
  text "Constant" at 8180.6,6821 h60
  text "Board Layer Stack" at 8750.46,6821 h60
  text "Top Overlay" at 5731.26,6701 h60
  text "Top Solder" at 5731.26,6581 h60
  text "Solder Resist" at 6671,6581 h60
  text "0.50mil" at 7530.77,6581 h60
  text "3.6" at 8180.6,6581 h60
  text "1" at 5321.35,6461 h60
  text "Top Layer" at 5731.26,6461 h60
  text "CF-004" at 6671,6461 h60
  text "1.40mil" at 7530.77,6461 h60
  text "Dielectric 1" at 5731.26,6341 h60
  text "FR-4" at 6671,6341 h60
  text "5.00mil" at 7530.77,6341 h60
  text "3.7" at 8180.6,6341 h60
  text "2" at 5321.35,6221 h60
  text "GND 2" at 5731.26,6221 h60
  text "CF-004" at 6671,6221 h60
  text "1.40mil" at 7530.77,6221 h60
  text "Dielectric 2" at 5731.26,6101 h60
  text "FR-4" at 6671,6101 h60
  text "10.00mil" at 7530.77,6101 h60
  text "3.7" at 8180.6,6101 h60
  text "3" at 5321.35,5981 h60
  text "Signal Layer 3" at 5731.26,5981 h60
  text "CF-004" at 6671,5981 h60
  text "1.40mil" at 7530.77,5981 h60
  text "Dielectric 3" at 5731.26,5861 h60
  text "FR-4" at 6671,5861 h60
  text "5.00mil" at 7530.77,5861 h60
  text "3.7" at 8180.6,5861 h60
  text "4" at 5321.35,5741 h60
  text "Power 4" at 5731.26,5741 h60
  text "CF-004" at 6671,5741 h60
  text "1.40mil" at 7530.77,5741 h60
  text "Dielectric 4" at 5731.26,5621 h60
  text "FR-4" at 6671,5621 h60
  text "10.00mil" at 7530.77,5621 h60
  text "3.7" at 8180.6,5621 h60
  text "5" at 5321.35,5501 h60
  text "Power 5" at 5731.26,5501 h60
  text "CF-004" at 6671,5501 h60
  text "1.40mil" at 7530.77,5501 h60
  text "Dielectric 5" at 5731.26,5381 h60
  text "FR-4" at 6671,5381 h60
  text "5.00mil" at 7530.77,5381 h60
  text "3.7" at 8180.6,5381 h60
  text "6" at 5321.35,5261 h60
  text "Signal Layer 6" at 5731.26,5261 h60
  text "CF-004" at 6671,5261 h60
  text "1.40mil" at 7530.77,5261 h60
  text "Dielectric 6" at 5731.26,5141 h60
  text "FR-4" at 6671,5141 h60
  text "10.00mil" at 7530.77,5141 h60
  text "3.7" at 8180.6,5141 h60
  text "7" at 5321.35,5021 h60
  text "GND 7" at 5731.26,5021 h60
  text "CF-004" at 6671,5021 h60
  text "1.40mil" at 7530.77,5021 h60
  text "Dielectric 7" at 5731.26,4901 h60
  text "FR-4" at 6671,4901 h60
  text "5.00mil" at 7530.77,4901 h60
  text "3.7" at 8180.6,4901 h60
  text "8" at 5321.35,4781 h60
  text "Bottom" at 5731.26,4781 h60
  text "CF-004" at 6671,4781 h60
  text "1.40mil" at 7530.77,4781 h60
  text "Bottom Solder" at 5731.26,4661 h60
  text "Solder Resist" at 6671,4661 h60
  text "0.50mil" at 7530.77,4661 h60
  text "3.6" at 8180.6,4661 h60
  text "Bottom Overlay" at 5731.26,4541 h60
  text ".Layer_Name" at -765.05,-899.49 h60
M13 Component Bodies Top:
  text ".Layer_Name" at -765.05,-899.49 h60
M14 Component Bodies Bottom:
  text ".Layer_Name" at -765.05,-899.49 h60
M15 Courtyards Top:
  text ".Layer_Name" at -765.05,-899.49 h60
M16 Courtyards Bottom:
  text ".Layer_Name" at -765.05,-899.49 h60
Drill Drawing:
  circle w10: c-1217.12,5961.33 r33.33
  circle w10: c-1217.12,5361.33 r20
  circle w10: c-1217.12,5361.33 r33.33
  lines w10: -1250.45,5194.67 -1233.79,5194.67 -1233.79,5178 -1200.45,5178 -1200.45,5194.67 -1183.79,5194.67 -1183.79,5228 -1200.45,5228 -1200.45,5244.67 -1233.79,5244.67 -1233.79,5228 -1250.45,5228 -1250.45,5194.67 ; -1250.45,5494.67 -1233.79,5494.67 -1217.12,5478 -1200.45,5494.67 -1183.79,5494.67 -1200.45,5511.33 -1183.79,5528 -1200.45,5528 -1217.12,5544.67 -1233.79,5528 -1250.45,5528 -1233.79,5511.33 -1250.45,5494.67 ; -1250.45,5628 -1217.12,5644.67 -1183.79,5628 -1200.45,5661.33 -1183.79,5694.67 -1217.12,5678 -1250.45,5694.67 -1233.79,5661.33 -1250.45,5628 ; -1250.45,5778 -1183.79,5778 -1183.79,5844.67 -1250.45,5844.67 -1250.45,5778 ; -1250.45,6144.67 -1183.79,6144.67 -1217.12,6078 -1250.45,6144.67 ; -1250.45,6261.33 -1217.12,6228 -1183.79,6261.33 -1217.12,6294.67 -1250.45,6261.33 ; -1250.45,6378 -1250.45,6394.67 -1233.79,6411.33 -1250.45,6428 -1250.45,6444.67 -1233.79,6444.67 -1217.12,6428 -1200.45,6444.67 -1183.79,6444.67 -1183.79,6428 -1200.45,6411.33 -1183.79,6394.67 -1183.79,6378 -1200.45,6378 -1217.12,6394.67 -1233.79,6378 -1250.45,6378
  lines w12: -1310.24,5133 4586.15,5133 ; -1310.24,6483 4586.15,6483 ; -759.37,4983 -759.37,6633 ; -109.54,4983 -109.54,6633 ; 1030.12,4983 1030.12,6633 ; 1536,4983 1536,6633 ; 2269.8,4983 2269.8,6633 ; 3459.46,4983 3459.46,6633 ; -1310.24,4983 4586.15,4983 4586.15,6633 -1310.24,6633 -1310.24,4983
  text "Symbol" at -1220.24,6528 h72
  text "Count" at -714.37,6528 h72
  text "Hole Size" at -64.54,6528 h72
  text "Plated" at 1075.12,6528 h72
  text "Hole Type" at 1581,6528 h72
  text "Drill Layer Pair" at 2314.8,6528 h72
  text "Hole Tolerance" at 3504.46,6528 h72
  text "18" at -714.37,6378 h60
  text "7.87mil (0.200mm)" at -64.54,6378 h60
  text "PTH" at 1075.12,6378 h60
  text "Round" at 1581,6378 h60
  text "Top Layer - Bottom" at 2314.8,6378 h60
  text "963" at -714.37,6228 h60
  text "8.00mil (0.203mm)" at -64.54,6228 h60
  text "PTH" at 1075.12,6228 h60
  text "Round" at 1581,6228 h60
  text "Top Layer - Bottom" at 2314.8,6228 h60
  text "28" at -714.37,6078 h60
  text "15.75mil (0.400mm)" at -64.54,6078 h60
  text "PTH" at 1075.12,6078 h60
  text "Round" at 1581,6078 h60
  text "Top Layer - Bottom" at 2314.8,6078 h60
  text "8" at -714.37,5928 h60
  text "23.62mil (0.600mm)" at -64.54,5928 h60
  text "PTH" at 1075.12,5928 h60
  text "Slot" at 1581,5928 h60
  text "Top Layer - Bottom" at 2314.8,5928 h60
  text "11" at -714.37,5778 h60
  text "25.00mil (0.635mm)" at -64.54,5778 h60
  text "PTH" at 1075.12,5778 h60
  text "Round" at 1581,5778 h60
  text "Top Layer - Bottom" at 2314.8,5778 h60
  text "10" at -714.37,5628 h60
  text "35.04mil (0.890mm)" at -64.54,5628 h60
  text "PTH" at 1075.12,5628 h60
  text "Round" at 1581,5628 h60
  text "Top Layer - Bottom" at 2314.8,5628 h60
  text "2" at -714.37,5478 h60
  text "35.43mil (0.900mm)" at -64.54,5478 h60
  text "NPTH" at 1075.12,5478 h60
  text "Round" at 1581,5478 h60
  text "Top Layer - Bottom" at 2314.8,5478 h60
  text "2" at -714.37,5328 h60
  text "45.00mil (1.143mm)" at -64.54,5328 h60
  text "PTH" at 1075.12,5328 h60
  text "Round" at 1581,5328 h60
  text "Top Layer - Bottom" at 2314.8,5328 h60
  text "4" at -714.37,5178 h60
  text "110.24mil (2.800mm)" at -64.54,5178 h60
  text "NPTH" at 1075.12,5178 h60
  text "Round" at 1581,5178 h60
  text "Top Layer - Bottom" at 2314.8,5178 h60
  text "+1.97mil/-1.18mil" at 3504.46,5178 h60
  text "1046 Total" at -714.37,5028 h60
  text "Slot definitions :" at -1220.24,4883.03 h60
  text "Routed Path Length" at -187.55,4883.03 h60
  text "= Calculated from tool start centre position to tool end centre position." at 915.11,4883.03 h60
  text "Hole Length" at -187.55,4783.05 h60
  text "= Routed Path Length + Tool Size = Slot length as defined in the PCB layout" at 505.25,4783.05 h60
  text ".Layer_Name" at -765.05,-899.49 h60
M17 Embedded Cavity:
  text ".Layer_Name" at -765.05,-899.49 h60
M18 Embedded Assembly:
  text ".Layer_Name" at -765.05,-899.49 h60
M19 Embedded Keepout:
  text ".Layer_Name" at -765.05,-899.49 h60

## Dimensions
-1342.05,-440.99 to -342.05,-440.99 on M2 Board Dimensions
4164.35,1387.95 to 1715.83,3364 on M2 Board Dimensions
1714.83,3400.25 to 5878.81,3400.25 on M2 Board Dimensions
4242.79,1354.25 to 5817.38,1050.29 on M2 Board Dimensions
